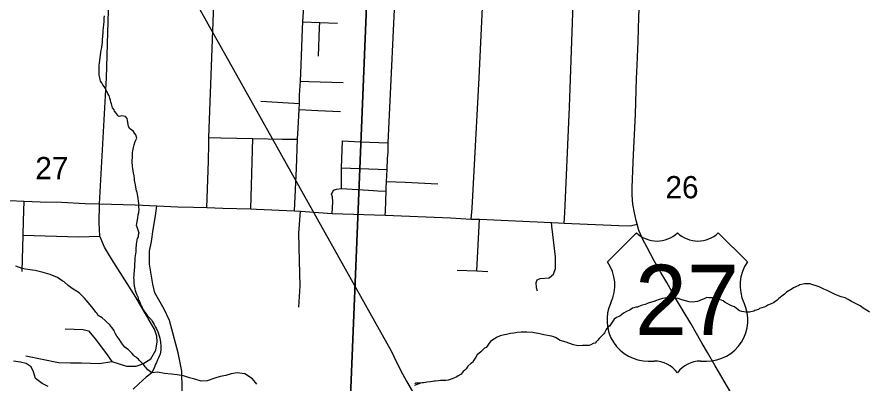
# Model space of a CAD drawing. Extents: x 0 to 34, y 0 to 22.
# Drawn here: x 3.4 to 5.004, y 18.922 to 19.613 of the extents above; entities that cross this region are included whole.
import ezdxf

# ---------------------------------------------------------------- set-up
doc = ezdxf.new("R2010")
doc.units = 0
for name, color, linetype in [('GM_X_City_Street', 7, 'Continuous'), ('GM_X_County_Road', 7, 'Continuous'), ('GM_X_Minor_River', 7, 'Continuous'), ('GM_X_Rail_Line', 7, 'Continuous'), ('GM_X_Section', 7, 'Continuous'), ('GM_X_Section_Text', 7, 'Continuous'), ('GM_X_State_Route', 7, 'Continuous'), ('GM_X_Township_Road', 7, 'Continuous'), ('GM_X_US_Location', 7, 'Continuous'), ('GM_X_US_Route', 7, 'Continuous'), ('GM_X_US_Shield', 7, 'Continuous')]:
    doc.layers.add(name, color=color, linetype=linetype)

msp = doc.modelspace()

# ---------------------------------------------------------------- linework, layer by layer
at = {"layer": 'GM_X_City_Street'}
for p, q in [((3.859, 19.4547), (3.9319, 19.4503)), ((3.8402, 19.2515), (3.8443, 19.3842)), ((4.0109, 19.3288), (4.0968, 19.3257)), ((4.266, 19.1352), (4.271, 19.232))]:
    msp.add_line(p, q, dxfattribs=at)
for points in [[(3.5646, 19.1798), (3.5556, 19.2005), (3.5545, 19.2251), (3.5555, 19.2612), (3.5684, 19.4983), (3.5753, 19.7319)], [(4.0935, 19.2396), (4.0939, 19.2473), (4.0951, 19.2853), (4.095, 19.2916), (4.096, 19.3033), (4.0968, 19.3257), (4.0979, 19.3464), (4.0988, 19.3586), (4.0991, 19.3677), (4.099, 19.3763), (4.1143, 19.7066)], [(4.2554, 19.2326), (4.2569, 19.2528), (4.2701, 19.4982), (4.2795, 19.6982)], [(4.4305, 19.2249), (4.4317, 19.244), (4.4403, 19.4432), (4.4492, 19.6919)], [(3.9384, 19.6041), (3.9699, 19.6029), (4.0035, 19.6015)], [(3.9674, 19.539), (3.9693, 19.593), (3.9699, 19.6029)], [(3.9339, 19.4922), (3.9494, 19.4918), (4.0141, 19.4899)], [(3.9313, 19.4387), (3.9663, 19.4368), (4.0089, 19.4351)], [(3.7612, 19.3861), (3.7837, 19.3857), (3.8443, 19.3842), (3.9, 19.3832), (3.9283, 19.3828)], [(4.0112, 19.2902), (4.0109, 19.3288), (4.0129, 19.3801)], [(4.0129, 19.3801), (4.0466, 19.378), (4.099, 19.3763)], [(4.096, 19.3033), (4.1307, 19.302), (4.1923, 19.2986)], [(3.9933, 19.2432), (3.9948, 19.2651), (3.994, 19.2746), (3.9924, 19.2792), (3.9932, 19.2815), (3.9959, 19.2868), (4.0017, 19.289), (4.0112, 19.2902), (4.0616, 19.2868), (4.0794, 19.2858), (4.0951, 19.2853)], [(3.4096, 19.1335), (3.4116, 19.2023), (3.4123, 19.229), (3.4132, 19.2664)], [(3.9308, 19.0667), (3.9332, 19.1069), (3.932, 19.1539), (3.9308, 19.2058), (3.9335, 19.2472)], [(4.38, 19.0965), (4.3779, 19.1029), (4.3775, 19.1133), (4.3796, 19.1178), (4.385, 19.1204), (4.4019, 19.1219), (4.4102, 19.1289), (4.4139, 19.1392), (4.4139, 19.1613), (4.4072, 19.219), (4.4066, 19.2263)], [(3.4116, 19.2023), (3.5154, 19.1993), (3.5556, 19.2005)], [(3.6471, 19.0454), (3.6446, 19.0498), (3.6235, 19.0856), (3.578, 19.1575), (3.5646, 19.1798)], [(4.2286, 19.1364), (4.266, 19.1352), (4.2866, 19.1339)], [(3.6518, 18.9691), (3.6615, 18.9858), (3.664, 19.0015), (3.6632, 19.0121), (3.659, 19.0251), (3.6471, 19.0454)], [(3.4903, 19.026), (3.5244, 19.0248), (3.5345, 19.0218), (3.5476, 19.0061), (3.5696, 18.9768), (3.5785, 18.9645)], [(3.4167, 18.9749), (3.4782, 18.9624), (3.5009, 18.9617), (3.5212, 18.9618), (3.5555, 18.9606), (3.5785, 18.9645), (3.6064, 18.9556), (3.6243, 18.9556), (3.6368, 18.9597), (3.6518, 18.9691)]]:
    msp.add_lwpolyline(points, dxfattribs=at)
at = {"layer": 'GM_X_County_Road'}
for points in [[(3.7571, 19.254), (3.7606, 19.3413), (3.761, 19.3744), (3.7612, 19.3861), (3.774, 19.7218)], [(3.0474, 19.269), (3.0839, 19.2749), (3.1052, 19.2762), (3.124, 19.2763), (3.1547, 19.2758), (3.2047, 19.2738), (3.2517, 19.2718), (3.2939, 19.2706), (3.3433, 19.2687), (3.3854, 19.2673), (3.4132, 19.2664), (3.4438, 19.2649), (3.4835, 19.2641), (3.5284, 19.2621), (3.5555, 19.2612), (3.6227, 19.2594), (3.6633, 19.2574)], [(3.6633, 19.2574), (3.7026, 19.2558), (3.7321, 19.2547), (3.7571, 19.254)], [(3.7571, 19.254), (3.7878, 19.2531), (3.8402, 19.2515)], [(3.8402, 19.2515), (3.8507, 19.251), (3.9226, 19.2477)], [(3.9226, 19.2477), (3.9335, 19.2472), (3.9933, 19.2432), (4.0935, 19.2396), (4.1397, 19.2378), (4.2165, 19.2347), (4.2554, 19.2326), (4.271, 19.232), (4.4066, 19.2263), (4.4197, 19.2255), (4.4305, 19.2249), (4.5332, 19.2202), (4.5546, 19.2199), (4.568, 19.223)]]:
    msp.add_lwpolyline(points, dxfattribs=at)
at = {"layer": 'GM_X_Minor_River'}
for points in [[(3.6249, 19.2197), (3.6258, 19.2246), (3.6263, 19.2277), (3.6273, 19.2345), (3.6279, 19.2406), (3.6295, 19.2451), (3.6297, 19.2512), (3.6295, 19.2546), (3.6292, 19.2573), (3.6293, 19.2619), (3.6287, 19.2661), (3.6281, 19.271), (3.6269, 19.2791), (3.6262, 19.2825), (3.6252, 19.2856), (3.6235, 19.2925), (3.6233, 19.2967), (3.6213, 19.3056), (3.621, 19.309), (3.6208, 19.3136), (3.6191, 19.3197), (3.6184, 19.3236), (3.6178, 19.3278), (3.6172, 19.3316), (3.6173, 19.3343), (3.617, 19.3381), (3.6167, 19.3415), (3.6174, 19.3495), (3.6175, 19.3537), (3.6176, 19.3571), (3.6181, 19.3609), (3.6191, 19.367), (3.6204, 19.3723), (3.6222, 19.3783), (3.6234, 19.3809), (3.6258, 19.3847), (3.6237, 19.3908), (3.6212, 19.394), (3.619, 19.3971), (3.6153, 19.4003), (3.6123, 19.4023), (3.6101, 19.4065), (3.6091, 19.4104), (3.6089, 19.415), (3.6079, 19.4184), (3.6072, 19.4219), (3.6039, 19.4258), (3.5975, 19.4268), (3.5948, 19.4265), (3.5921, 19.4258), (3.5895, 19.427), (3.5873, 19.4313), (3.5833, 19.4356), (3.5826, 19.4383), (3.58, 19.4419), (3.578, 19.4492), (3.5766, 19.4526), (3.5759, 19.4561), (3.5749, 19.4599), (3.5732, 19.4649), (3.571, 19.4684), (3.5696, 19.4719), (3.5678, 19.4747), (3.5664, 19.4781), (3.5642, 19.482), (3.5617, 19.4852), (3.5595, 19.489), (3.5573, 19.4922), (3.5563, 19.496), (3.5546, 19.5037), (3.5548, 19.5075), (3.5547, 19.517), (3.5549, 19.5223), (3.5554, 19.5261), (3.556, 19.5318), (3.5574, 19.5409), (3.558, 19.5466), (3.5581, 19.5504), (3.5594, 19.5557), (3.5609, 19.5663), (3.5611, 19.5709), (3.5619, 19.5827), (3.5624, 19.588), (3.5629, 19.5918), (3.5636, 19.5998), (3.5641, 19.6032), (3.5643, 19.6108), (3.5645, 19.615)], [(3.6249, 19.2197), (3.6292, 19.2065), (3.628, 19.2023), (3.6279, 19.1993), (3.6263, 19.1956), (3.6255, 19.1925), (3.6245, 19.1853), (3.6236, 19.1759), (3.6234, 19.1709), (3.622, 19.1596), (3.6215, 19.1535), (3.621, 19.149), (3.6209, 19.1425), (3.6198, 19.1289), (3.6197, 19.1262), (3.6193, 19.1224), (3.6196, 19.119), (3.6202, 19.1133), (3.6208, 19.1064), (3.6215, 19.1019), (3.6225, 19.0969), (3.6236, 19.0946), (3.625, 19.0911), (3.6279, 19.0846), (3.6282, 19.0812), (3.6304, 19.0773), (3.6336, 19.0689), (3.6355, 19.0662), (3.638, 19.0612), (3.6395, 19.0589), (3.6428, 19.0546), (3.6457, 19.0504), (3.6532, 19.0426), (3.6546, 19.0403), (3.6579, 19.0341), (3.6608, 19.0287), (3.6623, 19.0256), (3.6648, 19.0199), (3.6677, 19.0126), (3.6691, 19.008), (3.6698, 19.0042), (3.6701, 19.0011), (3.671, 18.9928), (3.6709, 18.9856), (3.6704, 18.9825), (3.6692, 18.978), (3.6684, 18.9757), (3.6663, 18.9712), (3.6644, 18.9675), (3.6627, 18.9626), (3.6604, 18.9592), (3.6595, 18.9558), (3.6583, 18.9524), (3.6539, 18.9428)], [(3.4849, 19.1163), (3.4759, 19.1222), (3.4624, 19.1282), (3.4582, 19.1295), (3.4491, 19.132), (3.4442, 19.1332), (3.4344, 19.1354), (3.4291, 19.1363), (3.4162, 19.1381), (3.4098, 19.1394), (3.3977, 19.1435)], [(3.6539, 18.9428), (3.6461, 18.9489), (3.6431, 18.9521), (3.6412, 18.9544), (3.639, 18.9579), (3.6353, 18.961), (3.6338, 18.9633), (3.6305, 18.9664), (3.6286, 18.9688), (3.6264, 18.9703), (3.6242, 18.9723), (3.6219, 18.9739), (3.6193, 18.9762), (3.6167, 18.9793), (3.6137, 18.9824), (3.6093, 18.9867), (3.6063, 18.9887), (3.6026, 18.9922), (3.6007, 18.9945), (3.5967, 18.9996), (3.5948, 19.0023), (3.5912, 19.0084), (3.5878, 19.0119), (3.5856, 19.0162), (3.5838, 19.0204), (3.5827, 19.0227), (3.5787, 19.0285), (3.5746, 19.0331), (3.5683, 19.039), (3.5657, 19.0413), (3.5601, 19.0464), (3.553, 19.0508), (3.55, 19.055), (3.5482, 19.0574), (3.5434, 19.0643), (3.5375, 19.0713), (3.5341, 19.0752), (3.5267, 19.0837), (3.5219, 19.0888), (3.5167, 19.0935), (3.5036, 19.1018), (3.4961, 19.1073), (3.489, 19.1143), (3.4849, 19.1163)], [(5.0054, 19.0572), (5.0028, 19.0591), (4.9934, 19.0647), (4.9901, 19.0674), (4.9879, 19.0694), (4.9766, 19.075), (4.9717, 19.0774), (4.9649, 19.0813), (4.9597, 19.0841), (4.9517, 19.0862), (4.9404, 19.0907), (4.9307, 19.0955), (4.9254, 19.0983), (4.9194, 19.1003), (4.9107, 19.1047), (4.9069, 19.1063), (4.8968, 19.1096), (4.8937, 19.1105), (4.8861, 19.1106), (4.8827, 19.1104), (4.877, 19.1094), (4.8743, 19.1087), (4.872, 19.1076), (4.8624, 19.1029), (4.8597, 19.101), (4.8489, 19.0949), (4.8454, 19.0912), (4.843, 19.0889), (4.8345, 19.0831), (4.8314, 19.0797), (4.8268, 19.0764), (4.8244, 19.0746), (4.8214, 19.0735), (4.8137, 19.0703), (4.8098, 19.0677), (4.8071, 19.0663), (4.7983, 19.0638), (4.796, 19.0624), (4.7895, 19.0603), (4.7872, 19.0592), (4.7792, 19.0575), (4.7765, 19.0572), (4.7723, 19.0573), (4.7689, 19.0577), (4.7651, 19.0582), (4.7602, 19.0598), (4.7546, 19.0638), (4.7509, 19.0673), (4.7456, 19.0693), (4.7332, 19.0757), (4.7295, 19.0785), (4.7268, 19.08), (4.717, 19.0822), (4.7136, 19.083), (4.7091, 19.0839), (4.7026, 19.0844), (4.6992, 19.0845), (4.6953, 19.0827), (4.6911, 19.0809), (4.6869, 19.0795), (4.6846, 19.0784), (4.6811, 19.077), (4.6766, 19.0767), (4.6712, 19.0761), (4.6659, 19.0766), (4.6591, 19.0783), (4.6519, 19.0804), (4.6448, 19.0829), (4.6391, 19.0838), (4.6353, 19.0846), (4.6304, 19.0847), (4.6277, 19.0844)], [(4.6277, 19.0844), (4.6239, 19.0841), (4.6193, 19.0835), (4.6155, 19.0828), (4.6074, 19.0804), (4.604, 19.0789), (4.5994, 19.0775), (4.5887, 19.074), (4.5829, 19.0719), (4.5772, 19.0701), (4.571, 19.068), (4.5687, 19.0669), (4.5657, 19.0666), (4.5588, 19.0645), (4.5545, 19.0619), (4.5522, 19.0601), (4.5491, 19.059), (4.5418, 19.055), (4.5391, 19.0528), (4.5349, 19.0499), (4.5287, 19.0474), (4.5244, 19.0437), (4.5181, 19.0347), (4.5154, 19.0306), (4.5127, 19.0288), (4.5092, 19.0247), (4.5083, 19.0221), (4.506, 19.0183), (4.5052, 19.0161), (4.4962, 19.0075), (4.4935, 19.0042), (4.4907, 19.0012), (4.4884, 18.9986), (4.485, 18.998), (4.4803, 18.9954), (4.4777, 18.9947), (4.4689, 18.9942), (4.4647, 18.9943), (4.4579, 18.9941), (4.4533, 18.9946), (4.448, 18.9955), (4.439, 18.9991), (4.4341, 19.0004), (4.4227, 19.0037), (4.4197, 19.006), (4.4152, 19.0088), (4.4111, 19.0108), (4.4062, 19.0121), (4.3922, 19.0147), (4.3873, 19.0156), (4.3812, 19.0169), (4.3778, 19.0177), (4.374, 19.0182), (4.371, 19.019), (4.36, 19.0197), (4.3558, 19.0198), (4.3493, 19.0196), (4.3421, 19.0186), (4.3356, 19.0176), (4.3291, 19.017), (4.3215, 19.0149), (4.318, 19.0146), (4.31, 19.0126), (4.3031, 19.0093), (4.3004, 19.0075), (4.2981, 19.0064), (4.2915, 19.002), (4.2891, 18.9986), (4.2856, 18.9934), (4.2833, 18.9908), (4.2802, 18.9894), (4.2732, 18.9827), (4.2666, 18.9768), (4.2638, 18.9723), (4.2599, 18.9667), (4.2575, 18.9626), (4.2544, 18.9604), (4.2486, 18.9552), (4.2458, 18.9507), (4.2431, 18.9478), (4.2404, 18.9452), (4.2361, 18.9407), (4.2307, 18.9374), (4.228, 18.9352), (4.2195, 18.9316), (4.2118, 18.9292), (4.2076, 18.9285), (4.2046, 18.9286), (4.2023, 18.9286), (4.1997, 18.9283), (4.1974, 18.9284), (4.1936, 18.9281), (4.1875, 18.9275), (4.1852, 18.9272), (4.1821, 18.9269), (4.1783, 18.9258), (4.1714, 18.9252), (4.1691, 18.9245), (4.1657, 18.9239), (4.1627, 18.9239), (4.1596, 18.9236)], [(3.4588, 18.9171), (3.4472, 18.9231), (3.4349, 18.9322), (3.431, 18.9448), (3.4267, 18.9544), (3.417, 18.9603), (3.4064, 18.9629), (3.3936, 18.9651)], [(3.8516, 18.9214), (3.8434, 18.9318), (3.8288, 18.9408), (3.8144, 18.943), (3.803, 18.9409), (3.793, 18.9377), (3.7828, 18.9363), (3.7725, 18.9331), (3.758, 18.928), (3.7469, 18.9275), (3.7349, 18.9311), (3.725, 18.9335), (3.7133, 18.9372), (3.7016, 18.9393), (3.6906, 18.9402), (3.6777, 18.9416), (3.6645, 18.9445), (3.6539, 18.9428), (3.6431, 18.9346), (3.6296, 18.9223), (3.6184, 18.9119)], [(4.1596, 18.9236), (4.1487, 18.9192)], [(4.1596, 18.9236), (4.157, 18.9237), (4.1543, 18.9238), (4.1512, 18.9235), (4.1489, 18.9224)]]:
    msp.add_lwpolyline(points, dxfattribs=at)
at = {"layer": 'GM_X_Rail_Line'}
msp.add_lwpolyline([(2.5538, 20.9), (2.6699, 20.7921), (2.9476, 20.533), (3.1327, 20.3614), (3.2237, 20.277), (3.3405, 20.1683), (3.4419, 20.0737), (3.4898, 20.0243), (3.5092, 20.0023), (3.5538, 19.9473), (3.6006, 19.8809), (3.6088, 19.8671), (3.6176, 19.8515), (3.6298, 19.8303), (3.6768, 19.7476), (3.7408, 19.633), (3.7622, 19.5944), (3.79, 19.5454), (4.1053, 18.9832), (4.1141, 18.9644), (4.1259, 18.9412), (4.1333, 18.9272), (4.1473, 18.9034)], dxfattribs=at)
at = {"layer": 'GM_X_Section'}
for points in [[(3.0692, 19.7796), (4.0623, 19.7415), (4.0218, 18.7461), (3.0273, 18.7832)], [(4.0623, 19.7415), (5.0674, 19.7096), (5.0264, 18.7096), (4.0218, 18.7461)]]:
    msp.add_lwpolyline(points, close=True, dxfattribs=at)
at = {"layer": 'GM_X_State_Route'}
for points in [[(3.9226, 19.2477), (3.9263, 19.3277), (3.9283, 19.3828), (3.9292, 19.4035), (3.9313, 19.4387), (3.9319, 19.4503), (3.9322, 19.466), (3.9339, 19.4922), (3.9349, 19.5231), (3.9376, 19.5907), (3.9384, 19.6041), (3.941, 19.652), (3.9432, 19.6924), (3.9443, 19.7132), (3.9462, 19.7451), (3.947, 19.7851), (3.9477, 19.7966), (3.9482, 19.8224), (3.95, 19.8562), (3.9506, 19.8844), (3.9523, 19.9306)], [(3.0474, 19.269), (3.0839, 19.2749), (3.1052, 19.2762), (3.124, 19.2763), (3.1547, 19.2758), (3.2047, 19.2738), (3.2517, 19.2718), (3.2939, 19.2706), (3.3433, 19.2687), (3.3854, 19.2673), (3.4132, 19.2664), (3.4438, 19.2649), (3.4835, 19.2641), (3.5284, 19.2621), (3.5555, 19.2612), (3.6227, 19.2594), (3.6633, 19.2574)], [(3.6633, 19.2574), (3.7026, 19.2558), (3.7321, 19.2547), (3.7571, 19.254)], [(3.7571, 19.254), (3.7878, 19.2531), (3.8402, 19.2515)], [(3.8402, 19.2515), (3.8507, 19.251), (3.9226, 19.2477)]]:
    msp.add_lwpolyline(points, dxfattribs=at)
at = {"layer": 'GM_X_Township_Road'}
msp.add_lwpolyline([(3.7051, 18.7441), (3.7053, 18.7481), (3.7069, 18.7785), (3.7084, 18.827), (3.7105, 18.8636), (3.7111, 18.8823), (3.7109, 18.9116), (3.71, 18.9461), (3.7034, 18.9808), (3.6868, 19.0418), (3.6771, 19.0626), (3.6594, 19.0934), (3.6557, 19.1098), (3.6491, 19.1475), (3.6494, 19.1722), (3.6533, 19.1904), (3.6565, 19.2129), (3.6608, 19.2383), (3.6633, 19.2574)], dxfattribs=at)
at = {"layer": 'GM_X_US_Route'}
for points in [[(4.5632, 19.404), (4.5644, 19.4301), (4.5668, 19.4969), (4.5676, 19.5221), (4.5698, 19.5674), (4.5711, 19.6128), (4.5729, 19.6551), (4.5735, 19.6877), (4.5748, 19.7235)], [(4.5706, 19.2134), (4.568, 19.223), (4.5661, 19.2301), (4.5627, 19.244), (4.5595, 19.2606), (4.5582, 19.2773), (4.5584, 19.2922), (4.5596, 19.3232), (4.561, 19.3543), (4.5627, 19.391), (4.5632, 19.404)], [(4.8694, 18.7052), (4.8606, 18.7181), (4.8342, 18.7572), (4.8004, 18.8101), (4.7801, 18.844), (4.7689, 18.8623), (4.7439, 18.9059), (4.7149, 18.956), (4.7001, 18.9811), (4.6902, 18.9985), (4.6686, 19.036), (4.64, 19.0836), (4.6234, 19.1132), (4.6123, 19.1319), (4.5996, 19.1539), (4.5858, 19.18), (4.579, 19.1929), (4.5716, 19.2096), (4.5706, 19.2134)]]:
    msp.add_lwpolyline(points, dxfattribs=at)
at = {"layer": 'GM_X_US_Shield'}
for p, q in [((4.5667, 19.2068), (4.5118, 19.1518)), ((4.7754, 19.1518), (4.7205, 19.2068)), ((4.5887, 18.9651), (4.5997, 18.9651)), ((4.6875, 18.9651), (4.6985, 18.9651))]:
    msp.add_line(p, q, dxfattribs=at)
for centre, radius, start, end in [((4.6052, 19.246), 0.0549, 225.573, 314.427), ((4.6821, 19.246), 0.0549, 225.573, 314.427), ((4.4488, 19.1077), 0.0769, 334.5471, 35.0009), ((4.8384, 19.1077), 0.0769, 144.9991, 205.4529), ((4.5878, 19.042), 0.0769, 154.8319, 270.6383), ((4.6994, 19.042), 0.0769, 269.3617, 25.1681), ((4.5997, 18.9101), 0.0549, 36.8699, 90), ((4.6875, 18.9101), 0.0549, 90, 143.1301)]:
    msp.add_arc(centre, radius, start, end, dxfattribs=at)

# ---------------------------------------------------------------- texts
at = {"layer": 'GM_X_Section_Text'}
for s, p in [('27', (3.4344, 19.3075)), ('26', (4.6211, 19.2716))]:
    msp.add_text(s, height=0.04186, rotation=0, dxfattribs=at).set_placement(p)
at = {"layer": 'GM_X_US_Location'}
for s, p in [('0', (4.6435, 19.0794)), ('/', (4.6436, 19.0794))]:
    msp.add_text(s, height=0.000189, dxfattribs=at).set_placement(p)
msp.add_text('27', height=0.000189, rotation=0, dxfattribs=at).set_placement((4.6044, 19.0402))
at = {"layer": 'GM_X_US_Shield'}
msp.add_text('27', height=0.13184, dxfattribs=at).set_placement((4.5636, 19.0145))

doc.saveas('drawing.dxf')
